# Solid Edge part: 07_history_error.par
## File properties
Author: edge
Template: jis part.par
Last saved by: edge
Revision: 7
Application: Solid Edge
文書内容のタイプ: 0
Accuracy: 0.990
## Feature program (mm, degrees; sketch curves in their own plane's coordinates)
sketch for "unnamed Protrusion 1" plane through (0, 10.5025, 10.5025) normal (1, 0, 0) x-axis (0, 1, 0)
  circle centre (-10.5025, -10.5025) radius 40
extrude "unnamed Protrusion 1" add finite 40 along +normal
sketch for "突き出し_2" plane through (40, 0, 0) normal (1, 0, 0) x-axis (0, 1, 0)
  circle centre (0, 0) radius 30
extrude "突き出し_2" add finite 20 along +normal
chamfer "面取り_1" setback 15
sketch for "突き出し_3" plane through (60, 0, 0) normal (1, 0, 0) x-axis (0, 1, 0)
  circle centre (0, 0) radius 20
extrude "突き出し_3" add finite 30 symmetric
sketch for "突き出し_4" plane through (0, 0, 0) normal (-1, 0, 0) x-axis (0, -1, 0)
  circle centre (0, 0) radius 30
extrude "突き出し_4" add finite 15 along +normal
sketch for "突き出し_5" plane through (-15, 0, 0) normal (-1, 0, 0) x-axis (0, -1, 0)
  circle centre (0, 0) radius 20
extrude "突き出し_5" add finite 20 along +normal
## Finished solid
Body 1: solid body, 11 faces, 10 edges, 0 vertices.
  Faces by surface: cylinder 5, plane 5, cone 1
  Edges by curve: circle 10
Bounding box of the edges (mm): 110.000 x 80.000 x 80.000, from (-35, -40, -40) to (75, 40, 40).
Cylindrical faces by radius (mm): R20 x2, R30 x2, R40 x1
Conical faces (half-angle, radius in mm at the cone's reference point): 45 deg R30 x1
Planar faces by outward normal: +x 2, -x 3
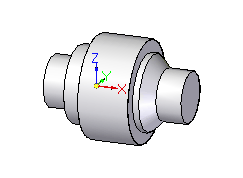
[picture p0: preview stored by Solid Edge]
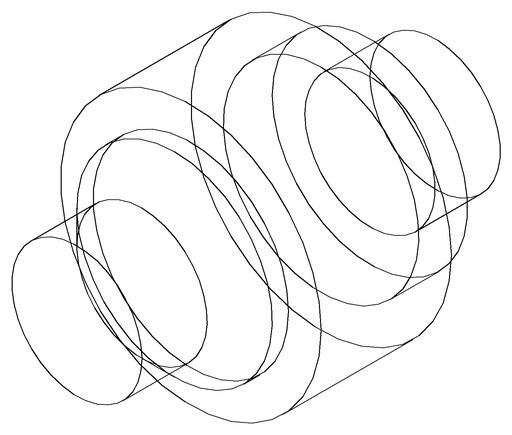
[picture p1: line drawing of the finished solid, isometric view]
